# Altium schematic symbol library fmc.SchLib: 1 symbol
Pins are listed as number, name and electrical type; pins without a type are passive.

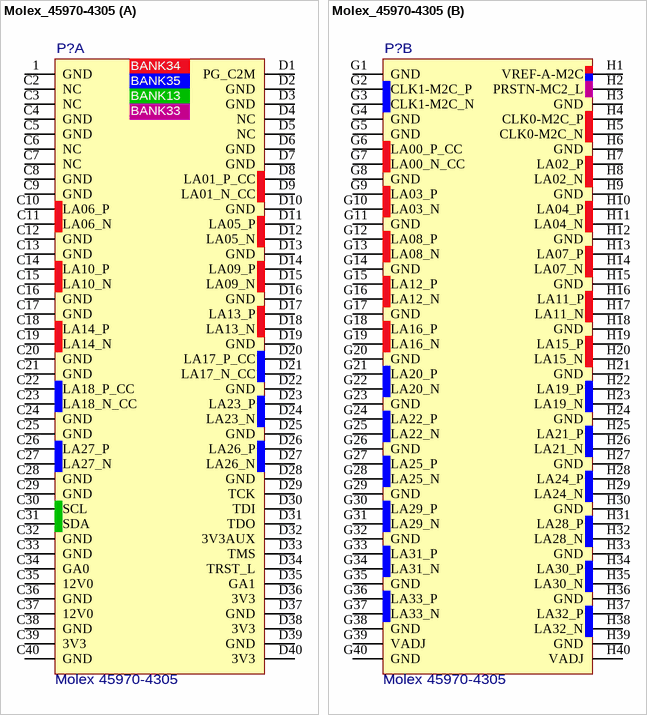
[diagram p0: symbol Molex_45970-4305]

## Molex_45970-4305
designator P?, comment Molex 45970-4305
1.27mm Pitch, SEARAY* Plug, 400 Circuits, 3.50mm Unmated Height, 10 Rows, with Pegs, Solder Charge™ Lead-Free, with Voids, per VITA-57
footprint Molex_45970-4305 (1.27mm Pitch, SEARAY* Plug, 400 Circuits, 3.50mm Unmated Height, 10 Rows, with Pegs, Solder Charge™ Lead-Free, with Voids, per VITA-57)
part A pins: 1 GND, C2 NC, C3 NC, C4 GND, C5 GND, C6 NC, C7 NC, C8 GND, C9 GND, C10 LA06_P, C11 LA06_N, C12 GND, C13 GND, C14 LA10_P, C15 LA10_N, C16 GND, C17 GND, C18 LA14_P, C19 LA14_N, C20 GND, C21 GND, C22 LA18_P_CC, C23 LA18_N_CC, C24 GND, C25 GND, C26 LA27_P, C27 LA27_N, C28 GND, C29 GND, C30 SCL, C31 SDA, C32 GND, C33 GND, C34 GA0, C35 12V0, C36 GND, C37 12V0, C38 GND, C39 3V3, C40 GND, D1 PG_C2M, D2 GND, D3 GND, D4 NC, D5 NC, D6 GND, D7 GND, D8 LA01_P_CC, D9 LA01_N_CC, D10 GND, D11 LA05_P, D12 LA05_N, D13 GND, D14 LA09_P, D15 LA09_N, D16 GND, D17 LA13_P, D18 LA13_N, D19 GND, D20 LA17_P_CC, D21 LA17_N_CC, D22 GND, D23 LA23_P, D24 LA23_N, D25 GND, D26 LA26_P, D27 LA26_N, D28 GND, D29 TCK, D30 TDI, D31 TDO, D32 3V3AUX, D33 TMS, D34 TRST_L, D35 GA1, D36 3V3, D37 GND, D38 3V3, D39 GND, D40 3V3
part B pins: G1 GND, G2 CLK1-M2C_P, G3 CLK1-M2C_N, G4 GND, G5 GND, G6 LA00_P_CC, G7 LA00_N_CC, G8 GND, G9 LA03_P, G10 LA03_N, G11 GND, G12 LA08_P, G13 LA08_N, G14 GND, G15 LA12_P, G16 LA12_N, G17 GND, G18 LA16_P, G19 LA16_N, G20 GND, G21 LA20_P, G22 LA20_N, G23 GND, G24 LA22_P, G25 LA22_N, G26 GND, G27 LA25_P, G28 LA25_N, G29 GND, G30 LA29_P, G31 LA29_N, G32 GND, G33 LA31_P, G34 LA31_N, G35 GND, G36 LA33_P, G37 LA33_N, G38 GND, G39 VADJ, G40 GND, H1 VREF-A-M2C, H2 PRSTN-MC2_L, H3 GND, H4 CLK0-M2C_P, H5 CLK0-M2C_N, H6 GND, H7 LA02_P, H8 LA02_N, H9 GND, H10 LA04_P, H11 LA04_N, H12 GND, H13 LA07_P, H14 LA07_N, H15 GND, H16 LA11_P, H17 LA11_N, H18 GND, H19 LA15_P, H20 LA15_N, H21 GND, H22 LA19_P, H23 LA19_N, H24 GND, H25 LA21_P, H26 LA21_N, H27 GND, H28 LA24_P, H29 LA24_N, H30 GND, H31 LA28_P, H32 LA28_N, H33 GND, H34 LA30_P, H35 LA30_N, H36 GND, H37 LA32_P, H38 LA32_N, H39 GND, H40 VADJ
